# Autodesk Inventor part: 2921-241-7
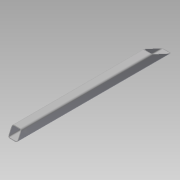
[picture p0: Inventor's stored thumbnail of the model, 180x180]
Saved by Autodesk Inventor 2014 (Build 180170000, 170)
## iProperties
Company: NHTSA/VRTC
Created: 2011-11
Part Number: 2921-241-7
Material: Steel
Document SubType Name: Modeling
Designer: Dave Walker
Density: 7.85 g/cm^3
Project: CHILD SIDE IMPACT SLED
Description: T.S. 2" x 2" x 1/8" x 816.1mm (32.13")
Mass: 3300.68 g
Surface Area: 2668.08 cm^2
Volume: 420.469 cm^3
Stock Number: IMPACTOR FRAME TUBE 7
Appearance: Steel
Author: Dave Walker
Title: Impactor Frame Tube 7
Subject: Child Sid eImpact Sled
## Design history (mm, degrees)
node "Sketch1"
node "2921-105-71"
workplane "Work Plane4"
node "2921-105-7"
node "Base1"
